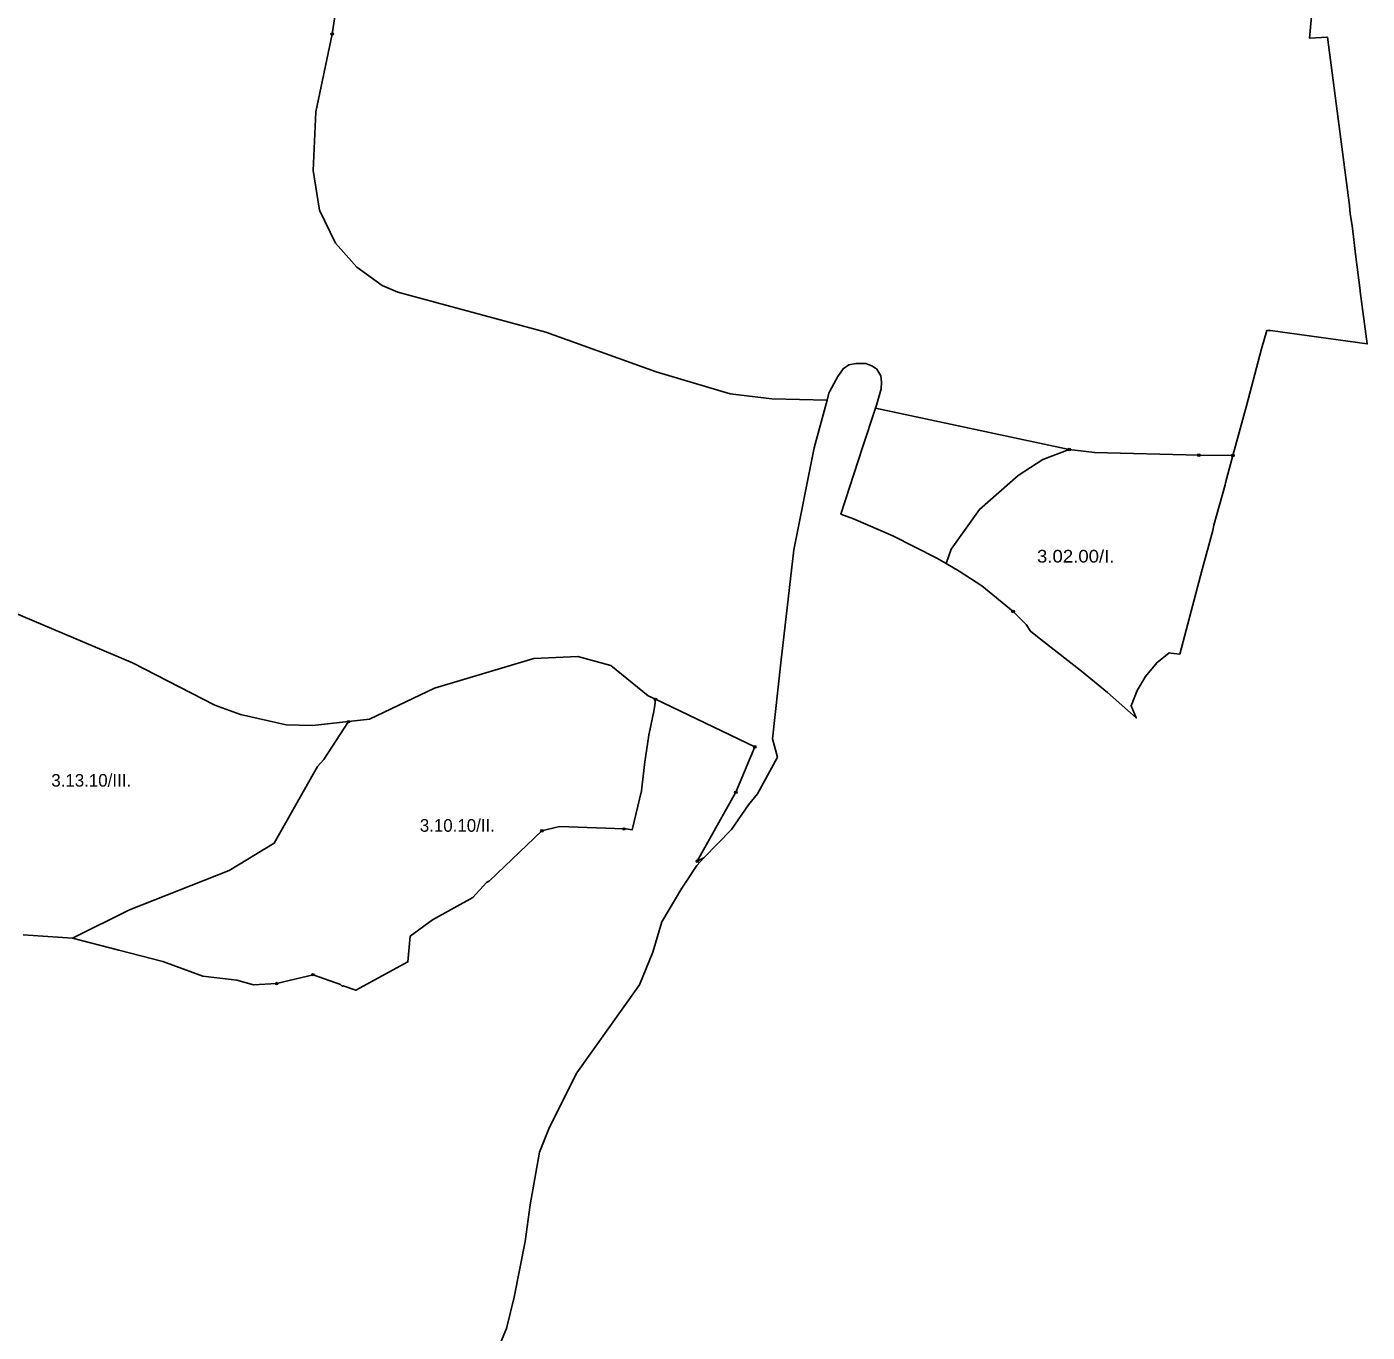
# Model space of a CAD drawing. Extents: x -650455 to -642254, y -1075222 to -1066610.
# Drawn here: x -648146 to -647085, y -1074176 to -1073142 of the extents above; entities that cross this region are included whole.
import ezdxf
from ezdxf.enums import TextEntityAlignment as Align

# ---------------------------------------------------------------- set-up
doc = ezdxf.new("R2010")
doc.units = 0
doc.header["$LTSCALE"] = 4
doc.header["$PDMODE"] = 32
doc.header["$PDSIZE"] = 2
for name, color, linetype, lineweight in [('1', 7, 'Continuous', 25), ('11', 7, 'Continuous', 13), ('12', 7, 'Continuous', 13), ('13', 7, 'Continuous', 13), ('16', 7, 'Continuous', 13)]:
    doc.layers.add(name, color=color, linetype=linetype, lineweight=lineweight)
doc.layers.add('2', color=7, linetype='Continuous')

msp = doc.modelspace()

# ---------------------------------------------------------------- linework, layer by layer
at = {"layer": '1'}
for points in [[(-647889.5, -1073048.5), (-647904.5, -1073148.001), (-647917.5, -1073209.501), (-647919.5, -1073256), (-647914.5, -1073287.5), (-647902, -1073313.501), (-647885, -1073332.5), (-647865, -1073347.001), (-647852.5, -1073352.5), (-647735.5, -1073384), (-647648, -1073415.501), (-647589.5, -1073433), (-647556.5, -1073437), (-647512.745, -1073437.818), (-647523.009, -1073475.688), (-647539.149, -1073556.382), (-647549.295, -1073645.879)], [(-647489.976, -1073408.948), (-647495.601, -1073410.03), (-647499.927, -1073413.062), (-647504.254, -1073419.123), (-647510.484, -1073430.899), (-647511.276, -1073432.397), (-647512.745, -1073437.818), (-647556.5, -1073437), (-647589.5, -1073433), (-647648, -1073415.501), (-647735.5, -1073384), (-647852.5, -1073352.5), (-647865, -1073347.001), (-647885, -1073332.5), (-647902, -1073313.501), (-647914.5, -1073287.5), (-647919.5, -1073256), (-647917.5, -1073209.501), (-647904.5, -1073148.001), (-647889.5, -1073048.5)], [(-647122.941, -1073068.189), (-647130.088, -1073142.652), (-647130.89, -1073151.357), (-647116.626, -1073150.512), (-647099.269, -1073283.721), (-647098.705, -1073290.495), (-647097.153, -1073299.526), (-647094.33, -1073324.363), (-647090.661, -1073351.173), (-647090.847, -1073351.875), (-647085.223, -1073393.44), (-647161.783, -1073382.641), (-647164.605, -1073382.642), (-647168.838, -1073397.177), (-647180.691, -1073442.334), (-647191.543, -1073481.728), (-647218.5, -1073481.5), (-647301, -1073479.501), (-647321, -1073477), (-647474.308, -1073444.149), (-647473.536, -1073441.853), (-647470.074, -1073429.081), (-647469.642, -1073423.67), (-647470.291, -1073418.689), (-647473.319, -1073413.278), (-647476.78, -1073410.896), (-647482.189, -1073408.948), (-647489.976, -1073408.948)], [(-648196, -1073589.501), (-648062.5, -1073646.001), (-647997.5, -1073679.5), (-647977, -1073687.001), (-647941, -1073695.001), (-647920, -1073695.5), (-647891.5, -1073692.5), (-647911, -1073722.501), (-647916.03, -1073728.11), (-647950.443, -1073788.764), (-647986, -1073810.5), (-648065, -1073841.5), (-648110, -1073864.001), (-648149.105, -1073861.45)], [(-647549.295, -1073645.879), (-647555.929, -1073706.229), (-647552.115, -1073720.775), (-647567.708, -1073749.687), (-647574.926, -1073758.495), (-647588.524, -1073777.822), (-647610.282, -1073800.427), (-647615.5, -1073803.001), (-647585, -1073748.5), (-647570, -1073712.5), (-647648.56, -1073674.85), (-647654.5, -1073672), (-647684, -1073648), (-647710, -1073641.001), (-647745, -1073642.501), (-647823.5, -1073666.001), (-647875, -1073690.501), (-647891.5, -1073692.5), (-647920, -1073695.5), (-647941, -1073695.001), (-647977, -1073687.001), (-647997.5, -1073679.5), (-648062.5, -1073646.001), (-648196, -1073589.501)], [(-647875, -1073690.501), (-647823.5, -1073666.001), (-647745, -1073642.501), (-647710, -1073641.001), (-647684, -1073648), (-647654.5, -1073672), (-647648.56, -1073674.85)], [(-647648.56, -1073674.85), (-647649.01, -1073679.36), (-647650.01, -1073684.42), (-647650.96, -1073689.171), (-647652.75, -1073698.15), (-647653.73, -1073703.07), (-647654.08, -1073705.051), (-647657.12, -1073724.42), (-647659.07, -1073742.58), (-647659.58, -1073747.371), (-647666.96, -1073778.14), (-647673.428, -1073777.101), (-647673.5, -1073777.5), (-647724.5, -1073775.501), (-647738.5, -1073779.001), (-647780, -1073818.5), (-647782.22, -1073819.921), (-647793.19, -1073831.831), (-647825.191, -1073849.38), (-647842.74, -1073862.31), (-647844.57, -1073882.821), (-647885.89, -1073905.24), (-647895.712, -1073901.66), (-647896.5, -1073902), (-647897.999, -1073900.817), (-647919.64, -1073892.921), (-647948.47, -1073899.97), (-647966.84, -1073901.04), (-647980, -1073897.156), (-648007, -1073894), (-648038.5, -1073882.5), (-648073.5, -1073873.501), (-648110, -1073864.001), (-648065, -1073841.5), (-647986, -1073810.5), (-647950.443, -1073788.764), (-647916.03, -1073728.11), (-647911, -1073722.501), (-647891.5, -1073692.5), (-647875, -1073690.501)], [(-647966.84, -1073901.04), (-647948.47, -1073899.97), (-647919.64, -1073892.921), (-647897.999, -1073900.817), (-647896.5, -1073902), (-647895.712, -1073901.66), (-647885.89, -1073905.24), (-647844.57, -1073882.821), (-647842.74, -1073862.31), (-647825.191, -1073849.38), (-647793.19, -1073831.831), (-647782.22, -1073819.921), (-647780, -1073818.5), (-647738.5, -1073779.001), (-647724.5, -1073775.501), (-647673.5, -1073777.5), (-647673.428, -1073777.101), (-647666.96, -1073778.14), (-647659.58, -1073747.371), (-647659.07, -1073742.58), (-647657.12, -1073724.42), (-647654.08, -1073705.051), (-647653.73, -1073703.07), (-647652.75, -1073698.15), (-647650.96, -1073689.171), (-647650.01, -1073684.42), (-647649.01, -1073679.36), (-647648.56, -1073674.85), (-647570, -1073712.5), (-647585, -1073748.5), (-647615.5, -1073803.001), (-647610.282, -1073800.427)], [(-647610.282, -1073800.427), (-647615.988, -1073806.355), (-647627.78, -1073824.409), (-647643.625, -1073851.181), (-647650.667, -1073875.134), (-647661.23, -1073900.849), (-647710.758, -1073970.544), (-647732.586, -1074013.768), (-647740.418, -1074033.399), (-647747.813, -1074075.318), (-647751.686, -1074104.202), (-647760.489, -1074148.235), (-647766.475, -1074173.244), (-647779.502, -1074203.89)], [(-648149.105, -1073861.45), (-648110, -1073864.001), (-648073.5, -1073873.501), (-648038.5, -1073882.5), (-648007, -1073894), (-647980, -1073897.156), (-647966.84, -1073901.04)]]:
    msp.add_lwpolyline(points, dxfattribs=at)
for points in [[(-647414.5, -1073556.001), (-647418.548, -1073567.245), (-647425.815, -1073563.032), (-647460.652, -1073545.317), (-647491.837, -1073531.962), (-647501.823, -1073528.217), (-647484.785, -1073475.301), (-647474.308, -1073444.149), (-647321, -1073477), (-647342, -1073485), (-647361.5, -1073497.5), (-647392, -1073524.501)], [(-647215.97, -1073572.157), (-647233.622, -1073639.105), (-647240.559, -1073638.303), (-647242.059, -1073638.13), (-647251.611, -1073645.862), (-647260.601, -1073656.828), (-647267.344, -1073667.795), (-647272.175, -1073680.016), (-647267.977, -1073689.516), (-647290.737, -1073669.383), (-647311.373, -1073652.56), (-647341.395, -1073629.138), (-647347.521, -1073624.289), (-647351.617, -1073620.751), (-647355.299, -1073615.471), (-647365.413, -1073605.349), (-647390.136, -1073585.104), (-647408.116, -1073573.294), (-647418.548, -1073567.245), (-647414.5, -1073556.001), (-647392, -1073524.501), (-647361.5, -1073497.5), (-647342, -1073485), (-647321, -1073477), (-647301, -1073479.501), (-647218.5, -1073481.5), (-647191.543, -1073481.728), (-647197.484, -1073503.293), (-647197.625, -1073504.988), (-647206.515, -1073536.879), (-647207.362, -1073541.112)]]:
    msp.add_lwpolyline(points, close=True, dxfattribs=at)
at = {"layer": '11'}
for points in [[(-647339.5, -1072889.001), (-647407.174, -1072877.482), (-647467.805, -1073000), (-647452.469, -1073000), (-647459.21, -1073004.071), (-647476.435, -1073003.416), (-647893.795, -1073076.991), (-647904.5, -1073148.001), (-647917.5, -1073209.501), (-647919.5, -1073256), (-647914.5, -1073287.5), (-647902, -1073313.501), (-647885, -1073332.5), (-647865, -1073347.001), (-647852.5, -1073352.5), (-647735.5, -1073384), (-647648, -1073415.501), (-647589.5, -1073433)], [(-647191.543, -1073481.728), (-647180.691, -1073442.334), (-647168.838, -1073397.177), (-647164.605, -1073382.642), (-647161.783, -1073382.641), (-647085.223, -1073393.44), (-647090.847, -1073351.875), (-647090.661, -1073351.173), (-647094.33, -1073324.363), (-647097.153, -1073299.526), (-647098.705, -1073290.495), (-647099.269, -1073283.721), (-647116.626, -1073150.512), (-647130.89, -1073151.357), (-647130.088, -1073142.652), (-647122.941, -1073068.189)], [(-647589.5, -1073433), (-647556.5, -1073437), (-647512.745, -1073437.818), (-647511.276, -1073432.397), (-647510.484, -1073430.899), (-647504.254, -1073419.123), (-647499.927, -1073413.062), (-647495.601, -1073410.03), (-647489.976, -1073408.948), (-647482.189, -1073408.948), (-647476.78, -1073410.896), (-647473.319, -1073413.278), (-647470.291, -1073418.689), (-647469.642, -1073423.67), (-647470.074, -1073429.081), (-647473.536, -1073441.853), (-647474.308, -1073444.149), (-647321, -1073477)], [(-647218.5, -1073481.5), (-647301, -1073479.501), (-647321, -1073477), (-647342, -1073485), (-647361.5, -1073497.5), (-647392, -1073524.501), (-647414.5, -1073556.001), (-647418.548, -1073567.245), (-647408.116, -1073573.294), (-647390.136, -1073585.104), (-647365.413, -1073605.349)], [(-647365.413, -1073605.349), (-647355.299, -1073615.471), (-647351.617, -1073620.751), (-647347.521, -1073624.289), (-647341.395, -1073629.138), (-647311.373, -1073652.56), (-647290.737, -1073669.383), (-647267.977, -1073689.516), (-647272.175, -1073680.016), (-647267.344, -1073667.795), (-647260.601, -1073656.828), (-647251.611, -1073645.862), (-647242.059, -1073638.13), (-647240.559, -1073638.303), (-647233.622, -1073639.105), (-647215.97, -1073572.157), (-647207.362, -1073541.112), (-647206.515, -1073536.879), (-647197.625, -1073504.988), (-647197.484, -1073503.293), (-647191.543, -1073481.728), (-647218.5, -1073481.5)], [(-647321, -1073477), (-647301, -1073479.501), (-647218.5, -1073481.5), (-647191.543, -1073481.728)]]:
    msp.add_lwpolyline(points, dxfattribs=at)
for p in [(-647321, -1073477), (-647218.5, -1073481.5), (-647191.543, -1073481.728), (-647365.413, -1073605.349)]:
    msp.add_point(p, dxfattribs=at)
at = {"layer": '12'}
msp.add_line((-647948.47, -1073899.97), (-647919.64, -1073892.921), dxfattribs=at)
for points in [[(-647648.56, -1073674.85), (-647654.5, -1073672), (-647684, -1073648), (-647710, -1073641.001), (-647745, -1073642.501), (-647823.5, -1073666.001), (-647875, -1073690.501), (-647891.5, -1073692.5)], [(-647673.5, -1073777.5), (-647673.428, -1073777.101), (-647666.96, -1073778.14), (-647659.58, -1073747.371), (-647659.07, -1073742.58), (-647657.12, -1073724.42), (-647654.08, -1073705.051), (-647653.73, -1073703.07), (-647652.75, -1073698.15), (-647650.96, -1073689.171), (-647650.01, -1073684.42), (-647649.01, -1073679.36), (-647648.56, -1073674.85)], [(-647891.5, -1073692.5), (-647911, -1073722.501), (-647916.03, -1073728.11), (-647950.443, -1073788.764), (-647986, -1073810.5), (-648065, -1073841.5), (-648110, -1073864.001), (-648073.5, -1073873.501), (-648038.5, -1073882.5), (-648007, -1073894), (-647980, -1073897.156), (-647966.84, -1073901.04), (-647948.47, -1073899.97)], [(-647738.5, -1073779.001), (-647724.5, -1073775.501), (-647673.5, -1073777.5)], [(-647919.64, -1073892.921), (-647897.999, -1073900.817), (-647896.5, -1073902), (-647895.712, -1073901.66), (-647885.89, -1073905.24), (-647844.57, -1073882.821), (-647842.74, -1073862.31), (-647825.191, -1073849.38), (-647793.19, -1073831.831), (-647782.22, -1073819.921), (-647780, -1073818.5), (-647738.5, -1073779.001)]]:
    msp.add_lwpolyline(points, dxfattribs=at)
for p in [(-647648.56, -1073674.85), (-647891.5, -1073692.5), (-647738.5, -1073779.001), (-647673.5, -1073777.5), (-647919.64, -1073892.921), (-647948.47, -1073899.97)]:
    msp.add_point(p, dxfattribs=at)
at = {"layer": '13'}
for points in [[(-647904.5, -1073148.001), (-647893.795, -1073076.991)], [(-647585, -1073748.5), (-647615.5, -1073803.001), (-647610.282, -1073800.427), (-647588.524, -1073777.822), (-647574.926, -1073758.495), (-647567.708, -1073749.687), (-647552.115, -1073720.775), (-647555.929, -1073706.229), (-647549.295, -1073645.879), (-647539.149, -1073556.382), (-647523.009, -1073475.688), (-647512.745, -1073437.818), (-647556.5, -1073437), (-647589.5, -1073433), (-647648, -1073415.501), (-647735.5, -1073384), (-647852.5, -1073352.5), (-647865, -1073347.001), (-647885, -1073332.5), (-647902, -1073313.501), (-647914.5, -1073287.5), (-647919.5, -1073256), (-647917.5, -1073209.501), (-647904.5, -1073148.001)], [(-648255, -1073570), (-648196, -1073589.501), (-648062.5, -1073646.001), (-647997.5, -1073679.5), (-647977, -1073687.001), (-647941, -1073695.001), (-647920, -1073695.5), (-647891.5, -1073692.5), (-647875, -1073690.501), (-647823.5, -1073666.001), (-647745, -1073642.501), (-647710, -1073641.001), (-647684, -1073648), (-647654.5, -1073672), (-647648.56, -1073674.85), (-647570, -1073712.5), (-647585, -1073748.5)], [(-648149.105, -1073861.45), (-648110, -1073864.001), (-648065, -1073841.5), (-647986, -1073810.5), (-647950.443, -1073788.764), (-647916.03, -1073728.11), (-647911, -1073722.501), (-647891.5, -1073692.5), (-647920, -1073695.5), (-647941, -1073695.001), (-647977, -1073687.001), (-647997.5, -1073679.5), (-648062.5, -1073646.001), (-648196, -1073589.501)]]:
    msp.add_lwpolyline(points, dxfattribs=at)
for p in [(-647904.5, -1073148.001), (-647585, -1073748.5)]:
    msp.add_point(p, dxfattribs=at)
at = {"layer": '16'}
for points in [[(-647570, -1073712.5), (-647648.56, -1073674.85), (-647649.01, -1073679.36), (-647650.01, -1073684.42), (-647650.96, -1073689.171), (-647652.75, -1073698.15), (-647653.73, -1073703.07), (-647654.08, -1073705.051), (-647657.12, -1073724.42), (-647659.07, -1073742.58), (-647659.58, -1073747.371), (-647666.96, -1073778.14), (-647673.428, -1073777.101), (-647673.5, -1073777.5), (-647724.5, -1073775.501), (-647738.5, -1073779.001), (-647780, -1073818.5), (-647782.22, -1073819.921), (-647793.19, -1073831.831), (-647825.191, -1073849.38), (-647842.74, -1073862.31), (-647844.57, -1073882.821), (-647885.89, -1073905.24), (-647895.712, -1073901.66), (-647896.5, -1073902), (-647897.999, -1073900.817), (-647919.64, -1073892.921), (-647948.47, -1073899.97), (-647966.84, -1073901.04), (-647980, -1073897.156), (-648007, -1073894), (-648038.5, -1073882.5), (-648073.5, -1073873.501), (-648110, -1073864.001), (-648149.105, -1073861.45)], [(-647615.5, -1073803.001), (-647585, -1073748.5), (-647570, -1073712.5)], [(-647779.502, -1074203.89), (-647766.475, -1074173.244), (-647760.489, -1074148.235), (-647751.686, -1074104.202), (-647747.813, -1074075.318), (-647740.418, -1074033.399), (-647732.586, -1074013.768), (-647710.758, -1073970.544), (-647661.23, -1073900.849), (-647650.667, -1073875.134), (-647643.625, -1073851.181), (-647627.78, -1073824.409), (-647615.988, -1073806.355), (-647610.282, -1073800.427), (-647615.5, -1073803.001)]]:
    msp.add_lwpolyline(points, dxfattribs=at)
for p in [(-647570, -1073712.5), (-647615.5, -1073803.001)]:
    msp.add_point(p, dxfattribs=at)

# ---------------------------------------------------------------- texts
at = {"layer": '2', "width": 1.1}
msp.add_text('3.02.00/I.', height=10, dxfattribs=at).set_placement((-647315.927, -1073566.523), align=Align.CENTER)
at = {"layer": '2'}
for s, p in [('3.13.10/III.', (-648095.245, -1073744.022)), ('3.10.10/II.', (-647805.409, -1073779.732))]:
    msp.add_text(s, height=10, dxfattribs=at).set_placement(p, align=Align.CENTER)

doc.saveas('drawing.dxf')
